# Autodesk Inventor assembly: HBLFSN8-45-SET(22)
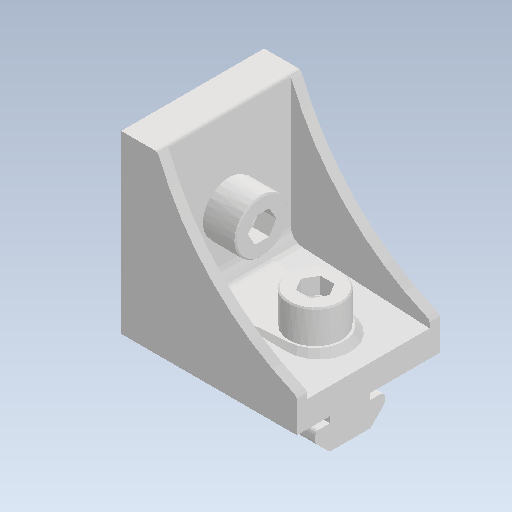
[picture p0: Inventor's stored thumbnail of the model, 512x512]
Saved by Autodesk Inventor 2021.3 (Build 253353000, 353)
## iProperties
Created: 2022-02
Part Number: HBLFSN8-45-SET(22)
Document SubType Name: Assembly
Designer: kengo
Author: kengo
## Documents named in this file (4)
- C:\Users\kengo\Documents\S2S_frame\SDC345\frame_misumi_ver12\HBLFSN8-45-SET(22).iam
- C:\Users\kengo\Documents\S2S_frame\SDC345\frame_misumi_ver12\HBLFSN8-45.ipt
- C:\Users\kengo\Documents\S2S_frame\SDC345\frame_misumi_ver12\HNTT8-8.ipt
- C:\Users\kengo\Documents\S2S_frame\SDC345\frame_misumi_ver12\CBM8-20.ipt
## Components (5 placed, 3 different names)
1. HBLFSN8-45
2. HNTT8-8
3. CBM8-20
4. HNTT8-8:1
5. CBM8-20:1
